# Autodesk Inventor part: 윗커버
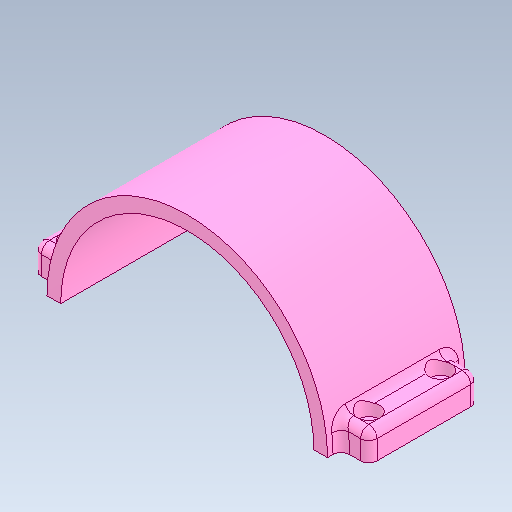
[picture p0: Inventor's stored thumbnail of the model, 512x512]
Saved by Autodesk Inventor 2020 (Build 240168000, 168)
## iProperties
Created: 2024-08
Part Number: 윗커버
Material: 알루미늄 6061
Document SubType Name: Modeling
Designer: oem
Density: 2.7 g/cm^3
Appearance: 기본값
Author: jhkim
Sending System: Autodesk Inventor 2025
Preprocessor: ST-DEVELOPER v20
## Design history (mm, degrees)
node "윗커버1"
node "솔리드2"
node "솔리드1"
